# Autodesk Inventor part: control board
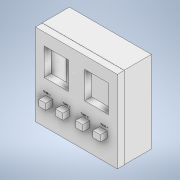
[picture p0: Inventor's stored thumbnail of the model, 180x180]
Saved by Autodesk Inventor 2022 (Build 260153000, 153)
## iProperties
Created: 2021-06
Part Number: control board
Material: PVC, Unplasticized
Document SubType Name: Modeling
Designer: adams
Density: 1.29 g/cm^3
Appearance: Smooth - White
Author: adams
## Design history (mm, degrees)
sketch "Sketch1"
  geometry: L1 (-71.718, 38.003)-(80.682, 38.003); L2 (80.682, 38.003)-(80.682, -114.397); L3 (80.682, -114.397)-(-71.718, -114.397); L4 (-71.718, -114.397)-(-71.718, 38.003); 1 further point
  constraints: 8 end point, 2 parallel, 1 horizontal, 1 perpendicular
  dimensions: "d0" = 152.4 distance of L1.start L1.end; "d1" = 152.4 distance of L1.end L2.end
extrude "Extrusion1" new body sketch "Sketch1" distance "d2" = 50.8; taper "d3" = 0 deg
sketch "Sketch2"
  geometry: L1 (-65.127, 31.19)-(74.573, 31.19); L2 (74.573, 31.19)-(74.573, -108.51); L3 (74.573, -108.51)-(-65.127, -108.51); L4 (-65.127, -108.51)-(-65.127, 31.19); 1 further point
  constraints: 8 end point, 2 parallel, 1 horizontal, 1 perpendicular
  dimensions: "d4" = 139.7 distance of L1.start L1.end; "d5" = 139.7 distance of L3.end L1.start
extrude "Extrusion2" cut sketch "Sketch2" distance "d6" = 38.1; taper "d7" = 0 deg
sketch "Sketch3"
  geometry: L1 (15.233, 35.933)-(66.033, 35.933); L2 (66.033, 35.933)-(66.033, 10.533); L3 (66.033, 10.533)-(15.233, 10.533); L4 (15.233, 10.533)-(15.233, 35.933); 1 further point
  constraints: 8 end point, 2 parallel, 1 horizontal, 1 perpendicular
  dimensions: "d8" = 50.8 distance of L1.start L1.end; "d9" = 25.4 distance of L1.end L2.end
extrude "Extrusion3" cut sketch "Sketch3" distance "d10" = 38.1; taper "d11" = 0 deg
sketch "Sketch4"
  geometry: L1 (-71.405, 37.83)-(80.995, 37.83); L2 (80.995, 37.83)-(80.995, -114.57); L3 (80.995, -114.57)-(-71.405, -114.57); L4 (-71.405, -114.57)-(-71.405, 37.83); 1 further point
  constraints: 8 end point, 2 parallel, 1 horizontal, 1 perpendicular
  dimensions: "d12" = 152.4 distance of L1.end L2.end; "d13" = 152.4 distance of L2.end L3.end
extrude "Extrusion4" join sketch "Sketch4" distance "d14" = 12.7; taper "d15" = 0 deg
sketch "Sketch5"
  geometry: L1 (-52.242, 16.044)-(-9.812, 16.044); L2 (-9.812, 16.044)-(-9.812, -23.469); L3 (-9.812, -23.469)-(-52.242, -23.469); L4 (-52.242, -23.469)-(-52.242, 16.044); L5 (31.557, 16.044)-(64.706, 16.044); L6 (64.706, 16.044)-(64.706, -23.469); L7 (64.706, -23.469)-(31.557, -23.469); L8 (31.557, -23.469)-(31.557, 16.044); L9 (-52.242, -62.717)-(-39.513, -62.717); L10 (-39.513, -62.717)-(-39.513, -74.12); L11 (-39.513, -74.12)-(-52.242, -74.12); L12 (-52.242, -74.12)-(-52.242, -62.717); L13 (-21.48, -62.717)-(-7.69, -62.717); L14 (-7.69, -62.717)-(-7.69, -74.12); L15 (-7.69, -74.12)-(-21.48, -74.12); L16 (-21.48, -74.12)-(-21.48, -62.717); L17 (15.911, -62.717)-(29.436, -62.717); L18 (29.436, -62.717)-(29.436, -74.12); L19 (29.436, -74.12)-(15.911, -74.12); L20 (15.911, -74.12)-(15.911, -62.717); L21 (48.132, -62.717)-(62.054, -62.717); L22 (62.054, -62.717)-(62.054, -74.12); L23 (62.054, -74.12)-(48.132, -74.12); L24 (48.132, -74.12)-(48.132, -62.717); 1 further point
  constraints: 48 end point, 12 parallel, 9 point on line, 6 horizontal, 6 perpendicular
extrude "Extrusion5" join sketch "Sketch5" distance "d16" = 12.7; taper "d17" = 0 deg
sketch "Sketch6"
  geometry: L1 (-55.159, 15.514)-(-10.077, 15.514); L2 (-10.077, 15.514)-(-10.077, -35.137); L3 (-10.077, -35.137)-(-55.159, -35.137); L4 (-55.159, -35.137)-(-55.159, 15.514); L5 (20.154, 15.514)-(64.441, 15.514); L6 (64.441, 15.514)-(64.441, -35.137); L7 (64.441, -35.137)-(20.154, -35.137); L8 (20.154, -35.137)-(20.154, 15.514); 1 further point
  constraints: 16 end point, 4 parallel, 2 horizontal, 2 perpendicular, 2 point on line
extrude "Extrusion6" cut sketch "Sketch6" distance "d18" = 12.7; taper "d19" = 0 deg
sketch "Sketch8"
  geometry: L1 (-57.31, -56.412)-(-33.967, -56.412); L2 (-33.967, -56.412)-(-33.967, -62.397); L3 (-33.967, -62.397)-(-57.31, -62.397); L4 (-57.31, -62.397)-(-57.31, -56.412); L5 (-20.5, -57.01)-(-2.843, -57.01); L6 (-2.843, -57.01)-(-2.843, -61.499); L7 (-2.843, -61.499)-(-20.5, -61.499); L8 (-20.5, -61.499)-(-20.5, -57.01); L9 (13.018, -57.01)-(31.872, -57.01); L10 (31.872, -57.01)-(31.872, -62.397); L11 (31.872, -62.397)-(13.018, -62.397); L12 (13.018, -62.397)-(13.018, -57.01); L13 (49.229, -55.813)-(66.288, -55.813); L14 (66.288, -55.813)-(66.288, -61.499); L15 (66.288, -61.499)-(49.229, -61.499); L16 (49.229, -61.499)-(49.229, -55.813); 1 further point
  constraints: 8 other
body "Solid1"
